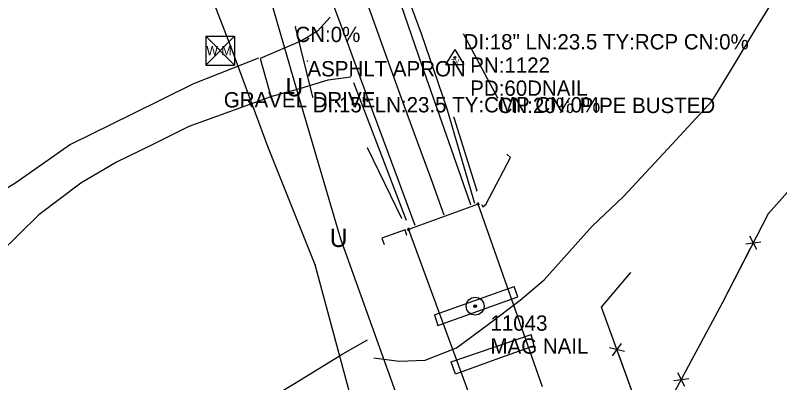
# Model space of a CAD drawing. Extents: x 1050807 to 1053552, y 395828 to 398415.
# Drawn here: x 1052065.9 to 1052315.2, y 397403.1 to 397522.9 of the extents above; entities that cross this region are included whole.
import ezdxf

# ---------------------------------------------------------------- set-up
doc = ezdxf.new("R2010")
doc.units = 0
for name, color, linetype in [('Default', 7, 'Continuous'), ('S_BRIDGE', 7, 'Continuous'), ('S_CROSS_DRAIN', 7, 'Continuous'), ('S_CROSS_DRAIN_ANNOT', 7, 'Continuous'), ('S_DITCHLINE', 7, 'Continuous'), ('S_DRG_PT_SYM', 7, 'Continuous'), ('S_DRIVEWAY', 7, 'Continuous'), ('S_EDGE_CONCRETE', 7, 'Continuous'), ('S_EDGE_PAVEMENT', 7, 'Continuous'), ('S_FENCE', 7, 'Continuous'), ('S_GUARDRAIL', 7, 'Continuous'), ('S_IRON_PIN', 7, 'Continuous'), ('S_IRON_PIN_ANNOT', 7, 'Continuous'), ('S_MSC_PT_SYM', 7, 'Continuous'), ('S_PAVEMENT_CROWN', 7, 'Continuous'), ('S_RDW_PT_SYM', 7, 'Continuous'), ('S_SECONDARY_CTL', 7, 'Continuous'), ('S_SECONDARY_CTL_ANNOT', 7, 'Continuous'), ('S_SHOULDER', 7, 'Continuous'), ('S_STR_PT_SYM', 7, 'Continuous'), ('S_SURVEY_TEXT_ANNOT', 7, 'Continuous'), ('S_UNDERGROUND_CABLE', 7, 'Continuous'), ('S_UTL_PT_SYM', 7, 'Continuous'), ('S_WATER_UTILITIES', 7, 'Continuous')]:
    doc.layers.add(name, color=color, linetype=linetype)

msp = doc.modelspace()

# ---------------------------------------------------------------- linework, layer by layer
at = {"layer": 'Default'}
for p, q in [((1052202.62, 397425.23), (1052228.58, 397434.44)), ((1052235.15, 397415.12), (1052234.13, 397418.85))]:
    msp.add_line(p, q, dxfattribs=at)
at = {"layer": 'S_BRIDGE'}
for p, q in [((1052216.82, 397461.36), (1052194.17, 397453.08)), ((1052237.9, 397401.73), (1052216.82, 397461.36)), ((1052194.17, 397453.08), (1052216.01, 397393.51))]:
    msp.add_line(p, q, dxfattribs=at)
at = {"layer": 'S_CROSS_DRAIN'}
for p, q in [((1052162.91, 397496.25), (1052157.24, 397519.19)), ((1052212.1, 397516.79), (1052223.22, 397496.03))]:
    msp.add_line(p, q, dxfattribs=at)
at = {"layer": 'S_DITCHLINE'}
for points in [[(1052182.87, 397411.17), (1052191.13, 397410.06), (1052199.54, 397410.4), (1052209.84, 397414.42), (1052220.22, 397422.2), (1052230.61, 397429.99), (1052238.34, 397436.67), (1052254.08, 397454.11), (1052264.3, 397463.78), (1052278.77, 397479.4), (1052293.24, 397495.01), (1052300.36, 397506.76), (1052307.49, 397518.52), (1052314.61, 397530.28), (1052321.73, 397542.03)], [(1051923.97, 397264.82), (1051934.15, 397286.32), (1051944.33, 397307.83), (1051958.22, 397321.57), (1051972.1, 397335.31), (1051985.98, 397349.06), (1051999.87, 397362.8), (1052014.51, 397368.54), (1052029.14, 397374.28), (1052043.96, 397375.01), (1052058.77, 397375.75), (1052082, 397374.5), (1052105.23, 397373.25), (1052125.17, 397384.42), (1052145.11, 397395.59), (1052158.93, 397404.03), (1052172.75, 397412.47), (1052180.81, 397417.01)]]:
    msp.add_lwpolyline(points, dxfattribs=at)
at = {"layer": 'S_DRG_PT_SYM'}
for points in [[(1052157.24, 397519.19), (1052157.24, 397519.24), (1052157.24, 397519.19), (1052157.19, 397519.19), (1052157.24, 397519.19), (1052157.24, 397519.14), (1052157.24, 397519.19), (1052157.29, 397519.19)], [(1052212.1, 397516.79), (1052212.1, 397516.84), (1052212.1, 397516.79), (1052212.05, 397516.79), (1052212.1, 397516.79), (1052212.1, 397516.74), (1052212.1, 397516.79), (1052212.15, 397516.79)], [(1052162.91, 397496.25), (1052162.91, 397496.3), (1052162.91, 397496.25), (1052162.86, 397496.25), (1052162.91, 397496.25), (1052162.91, 397496.2), (1052162.91, 397496.25), (1052162.96, 397496.25)], [(1052223.22, 397496.03), (1052223.22, 397496.08), (1052223.22, 397496.03), (1052223.17, 397496.03), (1052223.22, 397496.03), (1052223.22, 397495.98), (1052223.22, 397496.03), (1052223.27, 397496.03)]]:
    msp.add_lwpolyline(points, dxfattribs=at)
at = {"layer": 'S_DRIVEWAY'}
for points in [[(1052145.24, 397508.93), (1052124, 397500.53), (1052103.96, 397490.66), (1052083.92, 397480.8), (1052066, 397468.26), (1052052.01, 397459.72), (1052047.34, 397459.64)], [(1052148.91, 397496.27), (1052135.7, 397491.43), (1052122.5, 397486.6), (1052110.72, 397480.8), (1052098.93, 397475), (1052087.27, 397468.16), (1052073.58, 397457.8), (1052060.55, 397445.18), (1052054.3, 397439.83)]]:
    msp.add_lwpolyline(points, dxfattribs=at)
at = {"layer": 'S_EDGE_CONCRETE'}
for points in [[(1052218.09, 397461.22), (1052218.34, 397460.43), (1052219.31, 397461.19), (1052227.36, 397476.55), (1052226.23, 397477.62)], [(1052193.61, 397451.07), (1052193.09, 397452.98), (1052185.49, 397450.26), (1052186.25, 397448.12)], [(1052202.62, 397425.23), (1052203.71, 397421.69), (1052216.75, 397426.38), (1052229.79, 397431.06), (1052228.58, 397434.44)], [(1052235.15, 397415.12), (1052222.29, 397410.49), (1052209.44, 397405.87), (1052208.01, 397409.83), (1052221.07, 397414.34), (1052234.13, 397418.85)]]:
    msp.add_lwpolyline(points, dxfattribs=at)
at = {"layer": 'S_EDGE_PAVEMENT'}
for points in [[(1052214.47, 397461.1), (1052206.55, 397483.78), (1052198.62, 397506.45), (1052191.75, 397526.31), (1052184.88, 397546.16), (1052177.39, 397567.38), (1052169.89, 397588.61), (1052165.61, 397600.65), (1052161.33, 397612.68), (1052157.05, 397624.72), (1052152.78, 397636.76), (1052148.47, 397648.84), (1052144.17, 397660.93), (1052139.87, 397673.02), (1052135.57, 397685.11), (1052127.35, 397708.02), (1052119.13, 397730.93), (1052110.86, 397754.03), (1052102.59, 397777.13), (1052095.71, 397795.99), (1052088.82, 397814.85)], [(1052196.26, 397454.39), (1052187.61, 397477.79), (1052178.96, 397501.18), (1052174.52, 397513.15), (1052170.08, 397525.12), (1052165.65, 397537.09), (1052161.21, 397549.06), (1052156.87, 397561), (1052152.53, 397572.94), (1052148.19, 397584.89), (1052143.85, 397596.83), (1052135.54, 397619.78), (1052127.24, 397642.73), (1052119.19, 397665.09), (1052111.15, 397687.46), (1052106.97, 397699.31), (1052102.79, 397711.16), (1052098.61, 397723.02), (1052094.43, 397734.87), (1052086.32, 397757.66), (1052078.21, 397780.45), (1052073.59, 397792.48), (1052068.98, 397804.51)], [(1052168.53, 397522.36), (1052164.47, 397517.71), (1052159.21, 397514.6), (1052145.73, 397508.85), (1052149.2, 397496.41), (1052158.69, 397499.04), (1052167.88, 397501.87), (1052175.28, 397502.81)]]:
    msp.add_lwpolyline(points, dxfattribs=at)
at = {"layer": 'S_FENCE'}
for p, q in [((1052311.53, 397458.24), (1052346.09, 397497.15)), ((1052296.55, 397429.15), (1052311.53, 397458.24)), ((1052307.79, 397446.49), (1052305.46, 397450.91)), ((1052307.79, 397446.49), (1052305.46, 397450.91)), ((1052304.14, 397448.36), (1052309.1, 397449.03)), ((1052304.14, 397448.36), (1052309.1, 397449.03)), ((1052257.06, 397427.76), (1052266.57, 397438.95)), ((1052272.73, 397384.71), (1052296.55, 397429.15)), ((1052269.65, 397393.29), (1052257.06, 397427.76)), ((1052260.7, 397411.82), (1052263.57, 397415.9)), ((1052260.7, 397411.82), (1052263.57, 397415.9)), ((1052264.55, 397413.22), (1052259.72, 397414.5)), ((1052264.55, 397413.22), (1052259.72, 397414.5)), ((1052284.25, 397401.87), (1052282, 397406.33)), ((1052284.25, 397401.87), (1052282, 397406.33)), ((1052280.64, 397403.8), (1052285.61, 397404.4)), ((1052280.64, 397403.8), (1052285.61, 397404.4))]:
    msp.add_line(p, q, dxfattribs=at)
for points in [[(1052311.53, 397458.24), (1052324.82, 397473.19)], [(1052311.53, 397458.24), (1052324.82, 397473.19)], [(1052307.54, 397450.47), (1052311.53, 397458.24)], [(1052307.54, 397450.47), (1052311.53, 397458.24)], [(1052296.55, 397429.15), (1052305.71, 397446.92)], [(1052296.55, 397429.15), (1052305.71, 397446.92)], [(1052257.06, 397427.76), (1052266.57, 397438.95)], [(1052257.06, 397427.76), (1052266.57, 397438.95)], [(1052284.07, 397405.86), (1052296.55, 397429.15)], [(1052284.07, 397405.86), (1052296.55, 397429.15)], [(1052261.45, 397415.73), (1052257.06, 397427.76)], [(1052261.45, 397415.73), (1052257.06, 397427.76)], [(1052269.65, 397393.29), (1052262.82, 397411.99)], [(1052269.65, 397393.29), (1052262.82, 397411.99)]]:
    msp.add_lwpolyline(points, dxfattribs=at)
at = {"layer": 'S_GUARDRAIL'}
for p, q in [((1052208.92, 397489.59), (1052216.41, 397465.67)), ((1052191.96, 397456.64), (1052180.8, 397479.67))]:
    msp.add_line(p, q, dxfattribs=at)
at = {"layer": 'S_IRON_PIN'}
for radius in [2.91, 0.411, 0.262, 0.212, 0.145, 0.0822, 0.0581]:
    msp.add_circle((1052215.88, 397428.03), radius, dxfattribs=at)
at = {"layer": 'S_MSC_PT_SYM'}
for points in [[(1052161.18, 397507.99), (1052161.18, 397508.04), (1052161.18, 397507.99), (1052161.13, 397507.99), (1052161.18, 397507.99), (1052161.18, 397507.94), (1052161.18, 397507.99), (1052161.23, 397507.99)], [(1052133.89, 397497.85), (1052133.89, 397497.9), (1052133.89, 397497.85), (1052133.84, 397497.85), (1052133.89, 397497.85), (1052133.89, 397497.8), (1052133.89, 397497.85), (1052133.94, 397497.85)], [(1052311.53, 397458.24), (1052311.53, 397458.29), (1052311.53, 397458.24), (1052311.48, 397458.24), (1052311.53, 397458.24), (1052311.53, 397458.19), (1052311.53, 397458.24), (1052311.58, 397458.24)], [(1052266.57, 397438.95), (1052266.57, 397439), (1052266.57, 397438.95), (1052266.52, 397438.95), (1052266.57, 397438.95), (1052266.57, 397438.9), (1052266.57, 397438.95), (1052266.62, 397438.95)], [(1052296.55, 397429.15), (1052296.55, 397429.2), (1052296.55, 397429.15), (1052296.5, 397429.15), (1052296.55, 397429.15), (1052296.55, 397429.1), (1052296.55, 397429.15), (1052296.6, 397429.15)], [(1052257.06, 397427.76), (1052257.06, 397427.81), (1052257.06, 397427.76), (1052257.01, 397427.76), (1052257.06, 397427.76), (1052257.06, 397427.71), (1052257.06, 397427.76), (1052257.11, 397427.76)]]:
    msp.add_lwpolyline(points, dxfattribs=at)
at = {"layer": 'S_PAVEMENT_CROWN'}
msp.add_lwpolyline([(1052205.81, 397457.74), (1052201.49, 397469.54), (1052197.18, 397481.35), (1052192.86, 397493.15), (1052188.55, 397504.96), (1052180.47, 397527.64), (1052172.39, 397550.33), (1052164.11, 397573.46), (1052155.84, 397596.59), (1052149.3, 397615.07), (1052142.77, 397633.56), (1052138.44, 397645.49), (1052134.12, 397657.43), (1052129.8, 397669.37), (1052125.47, 397681.31), (1052121.16, 397693.43), (1052116.84, 397705.56), (1052112.53, 397717.68), (1052108.21, 397729.81), (1052100.29, 397752.14), (1052092.37, 397774.47), (1052083.81, 397797.39), (1052075.25, 397820.32)], dxfattribs=at)
at = {"layer": 'S_RDW_PT_SYM'}
for points in [[(1052208.92, 397489.59), (1052208.92, 397489.64), (1052208.92, 397489.59), (1052208.87, 397489.59), (1052208.92, 397489.59), (1052208.92, 397489.54), (1052208.92, 397489.59), (1052208.97, 397489.59)], [(1052180.8, 397479.67), (1052180.8, 397479.72), (1052180.8, 397479.67), (1052180.75, 397479.67), (1052180.8, 397479.67), (1052180.8, 397479.62), (1052180.8, 397479.67), (1052180.85, 397479.67)], [(1052216.41, 397465.67), (1052216.41, 397465.72), (1052216.41, 397465.67), (1052216.36, 397465.67), (1052216.41, 397465.67), (1052216.41, 397465.62), (1052216.41, 397465.67), (1052216.46, 397465.67)], [(1052191.96, 397456.64), (1052191.96, 397456.69), (1052191.96, 397456.64), (1052191.91, 397456.64), (1052191.96, 397456.64), (1052191.96, 397456.59), (1052191.96, 397456.64), (1052192.01, 397456.64)]]:
    msp.add_lwpolyline(points, dxfattribs=at)
at = {"layer": 'S_SECONDARY_CTL'}
for p, q in [((1052209.27, 397511.77), (1052206.26, 397506.82)), ((1052209.27, 397511.77), (1052212.22, 397506.82)), ((1052206.26, 397506.82), (1052212.22, 397506.82))]:
    msp.add_line(p, q, dxfattribs=at)
for radius in [0.311, 0.183, 0.103]:
    msp.add_circle((1052209.27, 397509.16), radius, dxfattribs=at)
at = {"layer": 'S_SHOULDER'}
for points in [[(1052215.81, 397461.5), (1052211.2, 397477.1), (1052206.6, 397492.7), (1052202.49, 397504.78), (1052198.38, 397516.87), (1052193.22, 397530.8), (1052188.06, 397544.72), (1052180.04, 397566.9), (1052172.01, 397589.08), (1052167.73, 397601.15), (1052163.45, 397613.21), (1052159.17, 397625.28), (1052154.9, 397637.34), (1052146.66, 397660.22), (1052138.43, 397683.1), (1052131.84, 397701.67)], [(1052193.51, 397455.96), (1052184.88, 397478.45), (1052176.26, 397500.94)]]:
    msp.add_lwpolyline(points, dxfattribs=at)
at = {"layer": 'S_STR_PT_SYM'}
for points in [[(1052216.82, 397461.36), (1052216.82, 397461.86), (1052216.82, 397461.36), (1052216.32, 397461.36), (1052216.82, 397461.36), (1052216.82, 397460.86), (1052216.82, 397461.36), (1052217.32, 397461.36)], [(1052194.17, 397453.08), (1052194.17, 397453.58), (1052194.17, 397453.08), (1052193.67, 397453.08), (1052194.17, 397453.08), (1052194.17, 397452.58), (1052194.17, 397453.08), (1052194.67, 397453.08)]]:
    msp.add_lwpolyline(points, dxfattribs=at)
at = {"layer": 'S_UNDERGROUND_CABLE'}
for p, q in [((1052157.64, 397499.02), (1052149.33, 397527.56)), ((1052172.07, 397449.89), (1052157.64, 397499.02)), ((1052194.51, 397387.53), (1052172.07, 397449.89))]:
    msp.add_line(p, q, dxfattribs=at)
at = {"layer": 'S_UTL_PT_SYM'}
for points in [[(1052136.18, 397512.78), (1052136.18, 397512.83), (1052136.18, 397512.78), (1052136.13, 397512.78), (1052136.18, 397512.78), (1052136.18, 397512.73), (1052136.18, 397512.78), (1052136.23, 397512.78)], [(1052148.28, 397480.11), (1052148.28, 397480.16), (1052148.28, 397480.11), (1052148.23, 397480.11), (1052148.28, 397480.11), (1052148.28, 397480.06), (1052148.28, 397480.11), (1052148.33, 397480.11)], [(1052163.71, 397441.57), (1052163.71, 397441.62), (1052163.71, 397441.57), (1052163.66, 397441.57), (1052163.71, 397441.57), (1052163.71, 397441.52), (1052163.71, 397441.57), (1052163.76, 397441.57)]]:
    msp.add_lwpolyline(points, dxfattribs=at)
at = {"layer": 'S_WATER_UTILITIES'}
for p, q in [((1052136.18, 397512.78), (1052119.03, 397556.83)), ((1052128, 397516.13), (1052137.34, 397516.13)), ((1052128, 397516.13), (1052128, 397506.64)), ((1052128, 397516.13), (1052137.34, 397506.64)), ((1052137.34, 397516.13), (1052128, 397506.64)), ((1052137.34, 397516.13), (1052137.34, 397506.64)), ((1052148.28, 397480.11), (1052136.18, 397512.78)), ((1052128, 397506.64), (1052137.34, 397506.64)), ((1052163.71, 397441.57), (1052148.28, 397480.11)), ((1052176.5, 397394.27), (1052163.71, 397441.57))]:
    msp.add_line(p, q, dxfattribs=at)

# ---------------------------------------------------------------- texts
at = {"layer": 'Default'}
for p in [(1052154.01, 397496.48), (1052168.44, 397447.35)]:
    msp.add_text('U', height=6, dxfattribs=at).set_placement(p)
at = {"layer": 'S_CROSS_DRAIN_ANNOT'}
for s, p in [('CN:0%', (1052157.24, 397514.19)), ('DI:18" LN:23.5 TY:RCP CN:0%', (1052212.1, 397511.79)), ('DI:15" LN:23.5 TY:CMP CN:0%', (1052162.91, 397491.25)), ('CN:20% PIPE BUSTED', (1052223.22, 397491.03))]:
    msp.add_text(s, height=5, dxfattribs=at).set_placement(p)
at = {"layer": 'S_IRON_PIN_ANNOT'}
for s, p in [('11043', (1052220.88, 397420.03)), ('MAG NAIL', (1052220.88, 397412.53))]:
    msp.add_text(s, height=5, dxfattribs=at).set_placement(p)
at = {"layer": 'S_SECONDARY_CTL'}
msp.add_text('TV', height=1.5, dxfattribs=at).set_placement((1052208.07, 397507.15))
at = {"layer": 'S_SECONDARY_CTL_ANNOT'}
for s, p in [('PN:1122', (1052214.27, 397504.16)), ('PD:60DNAIL', (1052214.27, 397496.66))]:
    msp.add_text(s, height=5, dxfattribs=at).set_placement(p)
at = {"layer": 'S_SURVEY_TEXT_ANNOT'}
for s, p in [('ASPHLT APRON', (1052161.18, 397502.99)), ('GRAVEL DRIVE', (1052133.89, 397492.85))]:
    msp.add_text(s, height=5, dxfattribs=at).set_placement(p)
at = {"layer": 'S_WATER_UTILITIES'}
msp.add_text('W M', height=3, dxfattribs=at).set_placement((1052128.21, 397509.9))

doc.saveas('drawing.dxf')
